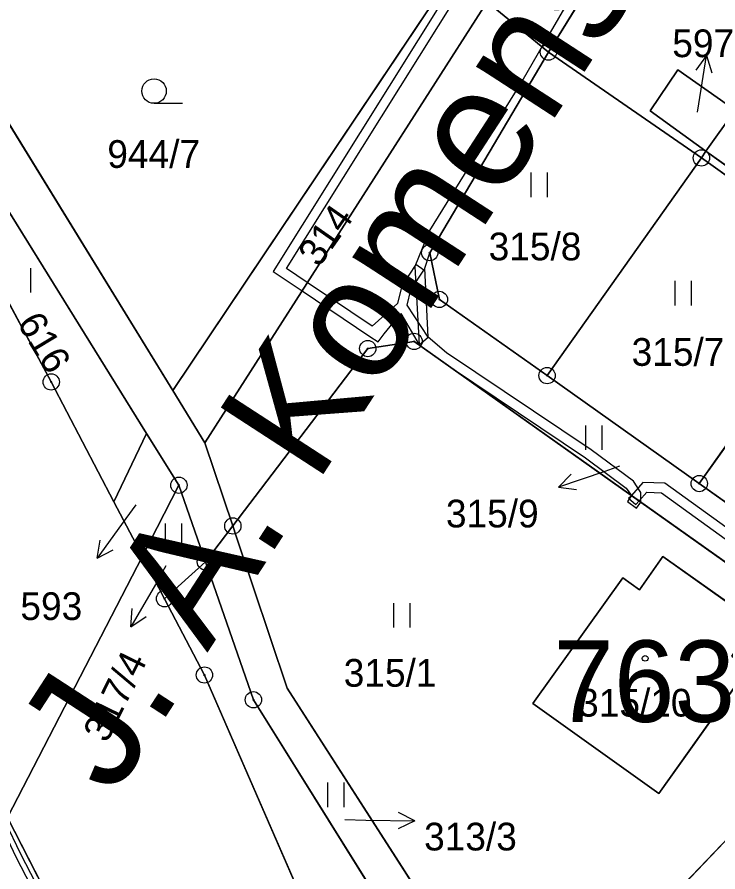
# Model space of a CAD drawing. Extents: x -689422 to -685210, y -987725 to -982160.
# Drawn here: x -687588.1 to -687545.1, y -985576.5 to -985524.1 of the extents above; entities that cross this region are included whole.
import ezdxf

# ---------------------------------------------------------------- set-up
doc = ezdxf.new("R2010")
doc.units = 0
for name, color, linetype in [('KN_Budovy', 7, 'Continuous'), ('KN_Budovy_cisla_domovni', 7, 'Continuous'), ('KN_Hranice_parcel', 7, 'Continuous'), ('KN_Parcelni cisla', 7, 'Continuous'), ('KN_Parcelni cisla_sipky', 7, 'Continuous'), ('KN_Polygon parcely', 7, 'Continuous'), ('KN_Popisy_pomistni nazvy nazvy ulic', 7, 'Continuous'), ('KN_POZEMKY_OSTATNI PLOCHA', 7, 'Continuous'), ('KN_POZEMKY_TTP', 7, 'Continuous'), ('KN_POZEMKY_ZAHRADA', 7, 'Continuous'), ('KN_POZEMKY_ZASTAVENA PLOCHA', 7, 'Continuous'), ('KN_VYUZITI_17_ostatni plocha_ostatni komunikace', 7, 'Continuous'), ('KN_VYUZITI_26_ostatni plocha_jina plocha', 7, 'Continuous'), ('KN_Věcná břemena k části', 7, 'Continuous'), ('KN_Značky bodu BP', 7, 'Continuous'), ('KN_Značky budov', 7, 'Continuous'), ('KN_Značky kultur', 7, 'Continuous')]:
    doc.layers.add(name, color=color, linetype=linetype)

msp = doc.modelspace()

# ---------------------------------------------------------------- linework, layer by layer
at = {"layer": 'KN_Budovy'}
msp.add_lwpolyline([(-687556.49, -985566.2), (-687548.75, -985571.72), (-687543.27, -985564.02), (-687544.29, -985563.3), (-687542.84, -985561.2), (-687548.52, -985557.19), (-687549.94, -985559.22), (-687550.97, -985558.49)], close=True, dxfattribs=at)
at = {"layer": 'KN_Hranice_parcel'}
for p, q in [((-687555.53, -985526.25), (-687537.03, -985496.36)), ((-687580.18, -985549.63), (-687599.7, -985518.21)), ((-687561.61, -985521.71), (-687578.57, -985547.01)), ((-687576.61, -985550.21), (-687559.33, -985523.23)), ((-687558.69, -985523.66), (-687555.53, -985526.25)), ((-687555.53, -985526.25), (-687546.15, -985532.74)), ((-687545.87, -985532.32), (-687544.07, -985529.82)), ((-687546.15, -985532.74), (-687545.87, -985532.32)), ((-687546.15, -985532.74), (-687555.61, -985546.09)), ((-687546.15, -985532.74), (-687536.83, -985539.38)), ((-687536.83, -985539.38), (-687546.28, -985552.71)), ((-687546.28, -985552.71), (-687555.61, -985546.09)), ((-687578.57, -985547.01), (-687576.61, -985550.21)), ((-687580.18, -985549.63), (-687582.18, -985553.83)), ((-687578.2, -985552.81), (-687580.18, -985549.63)), ((-687576.61, -985550.21), (-687574.89, -985555.31)), ((-687580.44, -985557.16), (-687578.2, -985552.81)), ((-687578.2, -985552.81), (-687576.57, -985557.51)), ((-687537.73, -985558.77), (-687546.28, -985552.71)), ((-687582.18, -985553.83), (-687580.44, -985557.16)), ((-687574.89, -985555.31), (-687576.57, -985557.51)), ((-687580.44, -985557.16), (-687588.72, -985573.19)), ((-687579.08, -985559.77), (-687580.44, -985557.16)), ((-687576.57, -985557.51), (-687579.08, -985559.77)), ((-687557.16, -985587.67), (-687534.93, -985564.43)), ((-687588.72, -985573.19), (-687568.91, -985611.81))]:
    msp.add_line(p, q, dxfattribs=at)
for points in [[(-687603.19, -985507.03), (-687601.77, -985509.26), (-687578.57, -985547.01)], [(-687582.18, -985553.83), (-687586.03, -985546.48), (-687590.02, -985539.06), (-687597.27, -985523.42), (-687599.7, -985518.21)], [(-687555.61, -985546.09), (-687562.22, -985541.42), (-687562.81, -985538.55), (-687555.53, -985526.25)], [(-687545.87, -985532.32), (-687549.29, -985529.85), (-687547.59, -985527.33), (-687544.07, -985529.82)], [(-687544.07, -985529.82), (-687540.98, -985532.01), (-687542.77, -985534.55), (-687545.87, -985532.32)], [(-687574.89, -985555.31), (-687566.61, -985544.43), (-687563.77, -985543.99), (-687534.93, -985564.43)], [(-687557.16, -985587.67), (-687571.55, -985565.25), (-687574.68, -985555.94), (-687574.89, -985555.31)], [(-687576.57, -985557.51), (-687573.63, -985565.97), (-687559.56, -985588.51), (-687558.79, -985589.38)], [(-687544.29, -985563.3), (-687543.27, -985564.02), (-687548.75, -985571.72), (-687556.49, -985566.2), (-687550.97, -985558.49), (-687549.94, -985559.22), (-687548.52, -985557.19), (-687542.84, -985561.2), (-687544.29, -985563.3)], [(-687563.59, -985594.39), (-687576.63, -985564.45), (-687579.08, -985559.77)]]:
    msp.add_lwpolyline(points, dxfattribs=at)
at = {"layer": 'KN_Parcelni cisla_sipky'}
for p, q in [((-687545.841, -985526.456), (-687546.492, -985527.367)), ((-687546.31, -985529.42), (-687545.841, -985526.456)), ((-687545.841, -985526.456), (-687545.503, -985527.523)), ((-687546.39, -985529.93), (-687546.31, -985529.42)), ((-687551.18, -985551.65), (-687552.08, -985551.96)), ((-687552.08, -985551.96), (-687554.917, -985552.937)), ((-687554.917, -985552.937), (-687554.134, -985552.138)), ((-687554.917, -985552.937), (-687553.808, -985553.084)), ((-687580.84, -985554.02), (-687581.45, -985554.86)), ((-687581.45, -985554.86), (-687583.214, -985557.288)), ((-687583.214, -985557.288), (-687583.03, -985556.183)), ((-687583.214, -985557.288), (-687582.22, -985556.772)), ((-687579, -985557.76), (-687579.64, -985558.89)), ((-687579.64, -985558.89), (-687581.14, -985561.489)), ((-687581.14, -985561.489), (-687581.073, -985560.371)), ((-687581.14, -985561.489), (-687580.206, -985560.872)), ((-687568.02, -985573.32), (-687566.73, -985573.35)), ((-687563.729, -985573.402), (-687564.722, -985572.884)), ((-687566.73, -985573.35), (-687563.729, -985573.402)), ((-687563.729, -985573.402), (-687564.74, -985573.886))]:
    msp.add_line(p, q, dxfattribs=at)
at = {"layer": 'KN_Polygon parcely'}
for points in [[(-687612.17, -985498.55), (-687634, -985464.12), (-687621.09, -985497.58), (-687606.65, -985532.39), (-687600.87, -985543.3), (-687595.89, -985557.7), (-687592.21, -985566.39), (-687590.46, -985569.81), (-687588.72, -985573.19), (-687580.44, -985557.16), (-687582.18, -985553.83), (-687586.03, -985546.48), (-687590.02, -985539.06), (-687597.27, -985523.42), (-687599.7, -985518.21)], [(-687585.22, -985484.27), (-687603.19, -985507.03), (-687601.77, -985509.26), (-687578.57, -985547.01), (-687561.61, -985521.71), (-687564.14, -985520.01)], [(-687542.96, -985497.58), (-687559.33, -985523.23), (-687558.69, -985523.66), (-687555.53, -985526.25), (-687537.03, -985496.36), (-687535.54, -985493.92), (-687538.61, -985489.55)], [(-687536.4, -985516.31), (-687543.15, -985512.7), (-687538.2, -985503.61), (-687531.52, -985507.27), (-687529.12, -985502.47), (-687530.42, -985500.75), (-687537.03, -985496.36), (-687555.53, -985526.25), (-687546.15, -985532.74), (-687545.87, -985532.32), (-687549.29, -985529.85), (-687547.59, -985527.33), (-687544.07, -985529.82), (-687536.85, -985517.14)], [(-687603.19, -985507.03), (-687609.65, -985496.92), (-687599.7, -985518.21), (-687580.18, -985549.63), (-687578.2, -985552.81), (-687576.57, -985557.51), (-687574.89, -985555.31), (-687576.61, -985550.21), (-687578.57, -985547.01), (-687601.77, -985509.26)], [(-687545.87, -985532.32), (-687546.15, -985532.74), (-687536.83, -985539.38), (-687521.53, -985512.59), (-687529.12, -985502.47), (-687531.52, -985507.27), (-687531.94, -985508.04), (-687525.18, -985511.64), (-687530.17, -985520.74), (-687536.85, -985517.14), (-687544.07, -985529.82), (-687540.98, -985532.01), (-687542.77, -985534.55)], [(-687580.18, -985549.63), (-687599.7, -985518.21), (-687597.27, -985523.42), (-687590.02, -985539.06), (-687586.03, -985546.48), (-687582.18, -985553.83)], [(-687576.61, -985550.21), (-687559.33, -985523.23), (-687561.61, -985521.71), (-687578.57, -985547.01)], [(-687546.28, -985552.71), (-687555.61, -985546.09), (-687562.22, -985541.42), (-687562.81, -985538.55), (-687555.53, -985526.25), (-687558.69, -985523.66), (-687559.33, -985523.23), (-687576.61, -985550.21), (-687574.89, -985555.31), (-687566.61, -985544.43), (-687563.77, -985543.99), (-687534.93, -985564.43), (-687521.31, -985574.08), (-687519.57, -985571.63), (-687528.25, -985565.49), (-687537.73, -985558.77)], [(-687555.53, -985526.25), (-687562.81, -985538.55), (-687562.22, -985541.42), (-687555.61, -985546.09), (-687546.15, -985532.74)], [(-687544.07, -985529.82), (-687547.59, -985527.33), (-687549.29, -985529.85), (-687545.87, -985532.32)], [(-687544.07, -985529.82), (-687545.87, -985532.32), (-687542.77, -985534.55), (-687540.98, -985532.01)], [(-687546.15, -985532.74), (-687555.61, -985546.09), (-687546.28, -985552.71), (-687536.83, -985539.38)], [(-687546.28, -985552.71), (-687537.73, -985558.77), (-687528.3, -985545.46), (-687536.83, -985539.38)], [(-687557.16, -985587.67), (-687534.93, -985564.43), (-687563.77, -985543.99), (-687566.61, -985544.43), (-687574.89, -985555.31), (-687574.68, -985555.94), (-687571.55, -985565.25)], [(-687578.2, -985552.81), (-687580.18, -985549.63), (-687582.18, -985553.83), (-687580.44, -985557.16)], [(-687580.44, -985557.16), (-687579.08, -985559.77), (-687576.57, -985557.51), (-687578.2, -985552.81)], [(-687576.57, -985557.51), (-687573.63, -985565.97), (-687559.56, -985588.51), (-687558.79, -985589.38), (-687557.16, -985587.67), (-687571.55, -985565.25), (-687574.68, -985555.94), (-687574.89, -985555.31)], [(-687579.08, -985559.77), (-687580.44, -985557.16), (-687588.72, -985573.19), (-687568.91, -985611.81), (-687559.8, -985603.08), (-687562.84, -985596.1), (-687563.59, -985594.39), (-687576.63, -985564.45)], [(-687576.57, -985557.51), (-687579.08, -985559.77), (-687576.63, -985564.45), (-687563.59, -985594.39), (-687558.79, -985589.38), (-687559.56, -985588.51), (-687573.63, -985565.97)], [(-687544.29, -985563.3), (-687543.27, -985564.02), (-687548.75, -985571.72), (-687556.49, -985566.2), (-687550.97, -985558.49), (-687549.94, -985559.22), (-687548.52, -985557.19), (-687542.84, -985561.2)], [(-687544.29, -985563.3), (-687542.84, -985561.2), (-687548.52, -985557.19), (-687549.94, -985559.22), (-687550.97, -985558.49), (-687556.49, -985566.2), (-687548.75, -985571.72), (-687543.27, -985564.02)], [(-687514.08, -985579.2), (-687521.31, -985574.08), (-687534.93, -985564.43), (-687557.16, -985587.67), (-687556.61, -985588.52), (-687542.19, -985606.05), (-687533.54, -985597.77), (-687518.88, -985586.17)], [(-687597.98, -985591.14), (-687574.19, -985616.86), (-687568.91, -985611.81), (-687588.72, -985573.19)]]:
    msp.add_lwpolyline(points, close=True, dxfattribs=at)
at = {"layer": 'KN_POZEMKY_OSTATNI PLOCHA'}
for p, q in [((-687537.03, -985496.36), (-687555.53, -985526.25)), ((-687601.77, -985509.26), (-687578.57, -985547.01)), ((-687580.18, -985549.63), (-687599.7, -985518.21)), ((-687578.57, -985547.01), (-687561.61, -985521.71)), ((-687559.33, -985523.23), (-687576.61, -985550.21)), ((-687555.53, -985526.25), (-687558.69, -985523.66)), ((-687549.29, -985529.85), (-687547.59, -985527.33)), ((-687547.59, -985527.33), (-687544.07, -985529.82)), ((-687545.87, -985532.32), (-687544.07, -985529.82)), ((-687544.07, -985529.82), (-687545.87, -985532.32)), ((-687545.87, -985532.32), (-687549.29, -985529.85)), ((-687542.77, -985534.55), (-687545.87, -985532.32)), ((-687590.02, -985539.06), (-687586.03, -985546.48)), ((-687586.03, -985546.48), (-687582.18, -985553.83)), ((-687576.61, -985550.21), (-687578.57, -985547.01)), ((-687578.57, -985547.01), (-687576.61, -985550.21)), ((-687582.18, -985553.83), (-687580.18, -985549.63)), ((-687580.18, -985549.63), (-687578.2, -985552.81)), ((-687578.2, -985552.81), (-687580.18, -985549.63)), ((-687576.61, -985550.21), (-687574.89, -985555.31)), ((-687578.2, -985552.81), (-687580.44, -985557.16)), ((-687576.57, -985557.51), (-687578.2, -985552.81)), ((-687582.18, -985553.83), (-687580.44, -985557.16)), ((-687580.44, -985557.16), (-687582.18, -985553.83)), ((-687574.89, -985555.31), (-687576.57, -985557.51)), ((-687588.72, -985573.19), (-687580.44, -985557.16)), ((-687580.44, -985557.16), (-687588.72, -985573.19)), ((-687580.44, -985557.16), (-687579.08, -985559.77)), ((-687579.08, -985559.77), (-687576.63, -985564.45)), ((-687576.63, -985564.45), (-687563.59, -985594.39)), ((-687568.91, -985611.81), (-687588.72, -985573.19))]:
    msp.add_line(p, q, dxfattribs=at)
at = {"layer": 'KN_POZEMKY_TTP'}
for p, q in [((-687555.53, -985526.25), (-687537.03, -985496.36)), ((-687599.7, -985518.21), (-687580.18, -985549.63)), ((-687576.61, -985550.21), (-687559.33, -985523.23)), ((-687558.69, -985523.66), (-687555.53, -985526.25)), ((-687555.53, -985526.25), (-687562.81, -985538.55)), ((-687562.81, -985538.55), (-687555.53, -985526.25)), ((-687546.15, -985532.74), (-687555.53, -985526.25)), ((-687555.53, -985526.25), (-687546.15, -985532.74)), ((-687547.59, -985527.33), (-687549.29, -985529.85)), ((-687544.07, -985529.82), (-687547.59, -985527.33)), ((-687549.29, -985529.85), (-687545.87, -985532.32)), ((-687546.15, -985532.74), (-687545.87, -985532.32)), ((-687545.87, -985532.32), (-687546.15, -985532.74)), ((-687545.87, -985532.32), (-687542.77, -985534.55)), ((-687546.15, -985532.74), (-687555.61, -985546.09)), ((-687555.61, -985546.09), (-687546.15, -985532.74)), ((-687536.83, -985539.38), (-687546.15, -985532.74)), ((-687546.15, -985532.74), (-687536.83, -985539.38)), ((-687562.81, -985538.55), (-687562.22, -985541.42)), ((-687562.22, -985541.42), (-687562.81, -985538.55)), ((-687586.03, -985546.48), (-687590.02, -985539.06)), ((-687546.28, -985552.71), (-687536.83, -985539.38)), ((-687536.83, -985539.38), (-687546.28, -985552.71)), ((-687562.22, -985541.42), (-687555.61, -985546.09)), ((-687555.61, -985546.09), (-687562.22, -985541.42)), ((-687574.89, -985555.31), (-687566.61, -985544.43)), ((-687566.61, -985544.43), (-687574.89, -985555.31)), ((-687566.61, -985544.43), (-687563.77, -985543.99)), ((-687563.77, -985543.99), (-687566.61, -985544.43)), ((-687563.77, -985543.99), (-687534.93, -985564.43)), ((-687534.93, -985564.43), (-687563.77, -985543.99)), ((-687582.18, -985553.83), (-687586.03, -985546.48)), ((-687555.61, -985546.09), (-687546.28, -985552.71)), ((-687546.28, -985552.71), (-687555.61, -985546.09)), ((-687580.18, -985549.63), (-687582.18, -985553.83)), ((-687574.89, -985555.31), (-687576.61, -985550.21)), ((-687580.44, -985557.16), (-687578.2, -985552.81)), ((-687578.2, -985552.81), (-687576.57, -985557.51)), ((-687537.73, -985558.77), (-687546.28, -985552.71)), ((-687546.28, -985552.71), (-687537.73, -985558.77)), ((-687576.57, -985557.51), (-687574.89, -985555.31)), ((-687574.68, -985555.94), (-687574.89, -985555.31)), ((-687574.89, -985555.31), (-687574.68, -985555.94)), ((-687571.55, -985565.25), (-687574.68, -985555.94)), ((-687574.68, -985555.94), (-687571.55, -985565.25)), ((-687579.08, -985559.77), (-687580.44, -985557.16)), ((-687576.57, -985557.51), (-687579.08, -985559.77)), ((-687579.08, -985559.77), (-687576.57, -985557.51)), ((-687576.57, -985557.51), (-687573.63, -985565.97)), ((-687573.63, -985565.97), (-687576.57, -985557.51)), ((-687548.52, -985557.19), (-687549.94, -985559.22)), ((-687542.84, -985561.2), (-687548.52, -985557.19)), ((-687550.97, -985558.49), (-687556.49, -985566.2)), ((-687549.94, -985559.22), (-687550.97, -985558.49)), ((-687576.63, -985564.45), (-687579.08, -985559.77)), ((-687534.93, -985564.43), (-687557.16, -985587.67)), ((-687557.16, -985587.67), (-687534.93, -985564.43)), ((-687548.75, -985571.72), (-687543.27, -985564.02)), ((-687563.59, -985594.39), (-687576.63, -985564.45)), ((-687557.16, -985587.67), (-687571.55, -985565.25)), ((-687571.55, -985565.25), (-687557.16, -985587.67)), ((-687573.63, -985565.97), (-687559.56, -985588.51)), ((-687559.56, -985588.51), (-687573.63, -985565.97)), ((-687556.49, -985566.2), (-687548.75, -985571.72)), ((-687588.72, -985573.19), (-687568.91, -985611.81))]:
    msp.add_line(p, q, dxfattribs=at)
at = {"layer": 'KN_POZEMKY_ZAHRADA'}
for p, q in [((-687578.57, -985547.01), (-687601.77, -985509.26)), ((-687561.61, -985521.71), (-687578.57, -985547.01))]:
    msp.add_line(p, q, dxfattribs=at)
at = {"layer": 'KN_POZEMKY_ZASTAVENA PLOCHA'}
for p, q in [((-687549.94, -985559.22), (-687548.52, -985557.19)), ((-687548.52, -985557.19), (-687542.84, -985561.2)), ((-687556.49, -985566.2), (-687550.97, -985558.49)), ((-687550.97, -985558.49), (-687549.94, -985559.22)), ((-687543.27, -985564.02), (-687548.75, -985571.72)), ((-687548.75, -985571.72), (-687556.49, -985566.2))]:
    msp.add_line(p, q, dxfattribs=at)
at = {"layer": 'KN_VYUZITI_17_ostatni plocha_ostatni komunikace'}
for p, q in [((-687537.03, -985496.36), (-687555.53, -985526.25)), ((-687601.77, -985509.26), (-687578.57, -985547.01)), ((-687580.18, -985549.63), (-687599.7, -985518.21)), ((-687578.57, -985547.01), (-687561.61, -985521.71)), ((-687559.33, -985523.23), (-687576.61, -985550.21)), ((-687555.53, -985526.25), (-687558.69, -985523.66)), ((-687590.02, -985539.06), (-687586.03, -985546.48)), ((-687586.03, -985546.48), (-687582.18, -985553.83)), ((-687576.61, -985550.21), (-687578.57, -985547.01)), ((-687578.57, -985547.01), (-687576.61, -985550.21)), ((-687582.18, -985553.83), (-687580.18, -985549.63)), ((-687580.18, -985549.63), (-687578.2, -985552.81)), ((-687578.2, -985552.81), (-687580.18, -985549.63)), ((-687576.61, -985550.21), (-687574.89, -985555.31)), ((-687578.2, -985552.81), (-687580.44, -985557.16)), ((-687576.57, -985557.51), (-687578.2, -985552.81)), ((-687582.18, -985553.83), (-687580.44, -985557.16)), ((-687580.44, -985557.16), (-687582.18, -985553.83)), ((-687574.89, -985555.31), (-687576.57, -985557.51)), ((-687588.72, -985573.19), (-687580.44, -985557.16)), ((-687580.44, -985557.16), (-687588.72, -985573.19)), ((-687580.44, -985557.16), (-687579.08, -985559.77)), ((-687579.08, -985559.77), (-687576.63, -985564.45)), ((-687576.63, -985564.45), (-687563.59, -985594.39)), ((-687568.91, -985611.81), (-687588.72, -985573.19))]:
    msp.add_line(p, q, dxfattribs=at)
at = {"layer": 'KN_VYUZITI_26_ostatni plocha_jina plocha'}
for p, q in [((-687549.29, -985529.85), (-687547.59, -985527.33)), ((-687547.59, -985527.33), (-687544.07, -985529.82)), ((-687545.87, -985532.32), (-687544.07, -985529.82)), ((-687544.07, -985529.82), (-687545.87, -985532.32)), ((-687545.87, -985532.32), (-687549.29, -985529.85)), ((-687542.77, -985534.55), (-687545.87, -985532.32))]:
    msp.add_line(p, q, dxfattribs=at)
at = {"layer": 'KN_Věcná břemena k části'}
for points in [[(-687536.96, -985496.25), (-687536.65, -985495.74), (-687537.02, -985495.5), (-687538.05, -985496.18), (-687546.67, -985510.52), (-687547.62, -985511.6), (-687555.93, -985525.92), (-687555.53, -985526.25), (-687553.96, -985523.71), (-687547.14, -985511.96), (-687546.19, -985510.88), (-687537.61, -985496.6)], [(-687550.32, -985552.57), (-687552.91, -985550.65), (-687561.78, -985544.69), (-687562.9, -985543.74), (-687563.12, -985539.5), (-687562.81, -985538.55), (-687555.53, -985526.25), (-687555.93, -985525.92), (-687557.09, -985527.91), (-687562.82, -985537.19), (-687563.72, -985539.4), (-687563.47, -985544.2), (-687561.47, -985545.62), (-687553.25, -985551.14), (-687550.76, -985552.99), (-687550.44, -985553.44), (-687549.86, -985553.85), (-687549.87, -985553.25)], [(-687550.44, -985553.44), (-687549.97, -985553.77), (-687549.49, -985553.24), (-687548.6, -985553.28), (-687537.02, -985561.63), (-687534.46, -985563.5), (-687533.69, -985564.92), (-687533.81, -985565.22), (-687533.31, -985565.58), (-687533.03, -985564.88), (-687534, -985563.1), (-687536.66, -985561.15), (-687548.4, -985552.68), (-687549.75, -985552.64)], [(-687549.86, -985553.85), (-687550.44, -985553.44), (-687550.69, -985553.8), (-687550.12, -985554.21)], [(-687550.62, -985553.6), (-687550.17, -985554), (-687549.97, -985553.77), (-687550.44, -985553.44)], [(-687568.18, -985611.11), (-687567.92, -985610.86), (-687568.38, -985610.11), (-687571.81, -985603.3), (-687574.17, -985598.83), (-687577.63, -985592.18), (-687580.73, -985586.63), (-687582.5, -985583.16), (-687583.85, -985581.78), (-687585.76, -985579.55), (-687587.9, -985575.44), (-687588.85, -985573.43), (-687589.04, -985573.82), (-687588.21, -985575.6), (-687586.05, -985579.75), (-687584.11, -985582.02), (-687582.76, -985583.35), (-687581, -985586.94), (-687577.93, -985592.35), (-687574.45, -985598.97), (-687568.66, -985610.34)]]:
    msp.add_lwpolyline(points, close=True, dxfattribs=at)
msp.add_lwpolyline([(-687561.74, -985522.64), (-687572.41, -985539.7), (-687570.64, -985540.89), (-687566.48, -985543.69), (-687565.97, -985544.01), (-687565.6, -985543.52), (-687564.58, -985542.28), (-687563.47, -985544.2), (-687562.9, -985543.74), (-687564.2, -985541.77), (-687563.97, -985540.82), (-687563.17, -985539.62), (-687563.67, -985539.28), (-687564.53, -985540.58), (-687564.79, -985541.66), (-687566.35, -985543.06), (-687570.32, -985540.38), (-687571.59, -985539.52), (-687561.11, -985522.76)], dxfattribs=at)
at = {"layer": 'KN_Značky bodu BP'}
for centre, radius in [((-687555.53, -985526.25), 0.5), ((-687555.53, -985526.25), 0.0303), ((-687546.15, -985532.74), 0.5), ((-687546.15, -985532.74), 0.0303), ((-687562.81, -985538.55), 0.5), ((-687562.81, -985538.55), 0.0303), ((-687562.22, -985541.42), 0.5), ((-687562.22, -985541.42), 0.0303), ((-687566.61, -985544.43), 0.5), ((-687563.77, -985543.99), 0.5), ((-687563.77, -985543.99), 0.0303), ((-687566.61, -985544.43), 0.0303), ((-687586.03, -985546.48), 0.5), ((-687555.61, -985546.09), 0.5), ((-687555.61, -985546.09), 0.0303), ((-687586.03, -985546.48), 0.0303), ((-687578.2, -985552.81), 0.5), ((-687546.28, -985552.71), 0.5), ((-687578.2, -985552.81), 0.0303), ((-687546.28, -985552.71), 0.0303), ((-687574.89, -985555.31), 0.5), ((-687574.89, -985555.31), 0.0303), ((-687576.57, -985557.51), 0.5), ((-687576.57, -985557.51), 0.0303), ((-687579.08, -985559.77), 0.5), ((-687579.08, -985559.77), 0.0303), ((-687576.63, -985564.45), 0.5), ((-687576.63, -985564.45), 0.0303), ((-687573.63, -985565.97), 0.5), ((-687573.63, -985565.97), 0.0303)]:
    msp.add_circle(centre, radius, dxfattribs=at)
at = {"layer": 'KN_Značky budov'}
msp.add_circle((-687549.597, -985563.429), 0.175, dxfattribs=at)
at = {"layer": 'KN_Značky kultur'}
for p, q in [((-687579.723, -985529.39), (-687577.973, -985529.39)), ((-687556.581, -985535.14), (-687556.581, -985533.64)), ((-687555.58, -985535.14), (-687555.58, -985533.64)), ((-687587.27, -985541), (-687587.27, -985539.5)), ((-687547.751, -985541.78), (-687547.751, -985540.28)), ((-687546.75, -985541.78), (-687546.75, -985540.28)), ((-687553.241, -985550.65), (-687553.241, -985549.15)), ((-687552.24, -985550.65), (-687552.24, -985549.15)), ((-687579.011, -985556.65), (-687579.011, -985555.15)), ((-687578.01, -985556.65), (-687578.01, -985555.15)), ((-687565.011, -985561.54), (-687565.011, -985560.04)), ((-687564.01, -985561.54), (-687564.01, -985560.04)), ((-687569.061, -985572.55), (-687569.061, -985571.05)), ((-687568.06, -985572.55), (-687568.06, -985571.05))]:
    msp.add_line(p, q, dxfattribs=at)
msp.add_circle((-687579.723, -985528.64), 0.75, dxfattribs=at)

# ---------------------------------------------------------------- texts
at = {"layer": 'KN_Budovy_cisla_domovni'}
msp.add_text('763', height=5, dxfattribs=at).set_placement((-687555.235, -985567.329))
at = {"layer": 'KN_Parcelni cisla'}
for s, p in [('597', (-687547.935, -985526.56)), ('944/7', (-687582.588, -985533.35)), ('315/8', (-687559.198, -985539.02)), ('315/7', (-687550.428, -985545.49)), ('315/9', (-687561.818, -985555.4)), ('593', (-687587.92, -985561.078)), ('315/1', (-687568.088, -985565.17)), ('315/10', (-687553.707, -985567)), ('313/3', (-687563.158, -985575.21))]:
    msp.add_text(s, height=1.7, dxfattribs=at).set_placement(p)
for s, rotation, p in [('314', 55, (-687569.603, -985539.507)), ('616', 301, (-687588.158, -985542.857)), ('317/4', 64, (-687582.612, -985568.677))]:
    msp.add_text(s, height=1.7, rotation=rotation, dxfattribs=at).set_placement(p)
at = {"layer": 'KN_Popisy_pomistni nazvy nazvy ulic'}
msp.add_text('J. A. Komenského', height=7.5, rotation=57, dxfattribs=at).set_placement((-687582.228, -985571.983))

doc.saveas('drawing.dxf')
